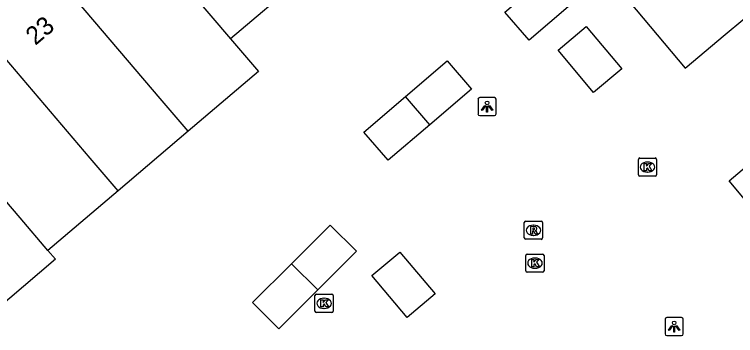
# Model space of a CAD drawing. Extents: x 160379 to 161131, y 383940 to 384849.
# Drawn here: x 160708.69 to 160748.4, y 384618.48 to 384636.19 of the extents above; entities that cross this region are included whole.
import ezdxf

# ---------------------------------------------------------------- set-up
doc = ezdxf.new("R2010")
doc.units = 0
for name, color, linetype in [('IMGEO_Kolk', 7, 'Continuous'), ('IMGEO_Lichtpunt', 7, 'Continuous'), ('IMGEO_Pand', 7, 'Continuous'), ('IMGEO_Pand_nummerreeks', 7, 'Continuous'), ('IMGEO_Rioolput', 7, 'Continuous')]:
    doc.layers.add(name, color=color, linetype=linetype)

msp = doc.modelspace()

# ---------------------------------------------------------------- linework, layer by layer
at = {"layer": 'IMGEO_Kolk'}
for p, q in [((160743.047, 384627.346), (160743.047, 384628.198)), ((160743.122, 384628.272), (160743.974, 384628.272)), ((160743.535, 384628.052), (160743.56, 384628.052)), ((160744.048, 384628.198), (160744.048, 384627.346)), ((160743.974, 384627.272), (160743.122, 384627.272)), ((160743.558, 384627.492), (160743.533, 384627.492)), ((160736.852, 384622.052), (160736.852, 384622.904)), ((160736.927, 384622.978), (160737.779, 384622.978)), ((160737.853, 384622.904), (160737.853, 384622.052)), ((160737.34, 384622.758), (160737.365, 384622.758)), ((160737.363, 384622.198), (160737.338, 384622.198)), ((160737.779, 384621.978), (160736.927, 384621.978)), ((160725.239, 384619.835), (160725.239, 384620.687)), ((160725.314, 384620.761), (160726.166, 384620.761)), ((160725.727, 384620.541), (160725.752, 384620.541)), ((160726.24, 384620.687), (160726.24, 384619.835)), ((160726.166, 384619.761), (160725.314, 384619.761)), ((160725.75, 384619.981), (160725.725, 384619.981))]:
    msp.add_line(p, q, dxfattribs=at)
for points in [[(160743.047, 384627.346), (160743.047, 384628.198)], [(160743.122, 384628.272), (160743.974, 384628.272)], [(160744.048, 384628.198), (160744.048, 384627.346)], [(160743.368, 384627.972), (160743.491, 384627.972), (160743.491, 384627.821), (160743.621, 384627.972), (160743.785, 384627.972), (160743.639, 384627.821), (160743.792, 384627.572), (160743.64, 384627.572), (160743.555, 384627.736), (160743.491, 384627.669), (160743.491, 384627.572), (160743.368, 384627.572), (160743.368, 384627.972)], [(160743.974, 384627.272), (160743.122, 384627.272)], [(160736.852, 384622.052), (160736.852, 384622.904)], [(160736.927, 384622.978), (160737.779, 384622.978)], [(160737.853, 384622.904), (160737.853, 384622.052)], [(160737.173, 384622.678), (160737.296, 384622.678), (160737.296, 384622.527), (160737.426, 384622.678), (160737.59, 384622.678), (160737.444, 384622.527), (160737.597, 384622.278), (160737.445, 384622.278), (160737.36, 384622.442), (160737.296, 384622.375), (160737.296, 384622.278), (160737.173, 384622.278), (160737.173, 384622.678)], [(160737.779, 384621.978), (160736.927, 384621.978)], [(160725.239, 384619.835), (160725.239, 384620.687)], [(160725.314, 384620.761), (160726.166, 384620.761)], [(160725.56, 384620.461), (160725.683, 384620.461), (160725.683, 384620.31), (160725.813, 384620.461), (160725.977, 384620.461), (160725.831, 384620.31), (160725.984, 384620.061), (160725.832, 384620.061), (160725.747, 384620.225), (160725.683, 384620.158), (160725.683, 384620.061), (160725.56, 384620.061), (160725.56, 384620.461)], [(160726.24, 384620.687), (160726.24, 384619.835)], [(160726.166, 384619.761), (160725.314, 384619.761)]]:
    msp.add_lwpolyline(points, dxfattribs=at)
for centre, start, end in [((160743.124, 384628.196), 91.552, 178.448), ((160743.124, 384628.196), 91.552, 178.448), ((160743.972, 384628.196), 1.552, 88.448), ((160743.972, 384628.196), 1.552, 88.448), ((160743.124, 384627.348), 181.552, 268.448), ((160743.124, 384627.348), 181.552, 268.448), ((160743.972, 384627.348), 271.552, 358.448), ((160743.972, 384627.348), 271.552, 358.448), ((160736.929, 384622.902), 91.552, 178.448), ((160736.929, 384622.902), 91.552, 178.448), ((160737.777, 384622.902), 1.552, 88.448), ((160737.777, 384622.902), 1.552, 88.448), ((160736.929, 384622.054), 181.552, 268.448), ((160736.929, 384622.054), 181.552, 268.448), ((160737.777, 384622.054), 271.552, 358.448), ((160737.777, 384622.054), 271.552, 358.448), ((160725.316, 384620.685), 91.552, 178.448), ((160725.316, 384620.685), 91.552, 178.448), ((160726.164, 384620.685), 1.552, 88.448), ((160726.164, 384620.685), 1.552, 88.448), ((160725.316, 384619.837), 181.552, 268.448), ((160725.316, 384619.837), 181.552, 268.448), ((160726.164, 384619.837), 271.552, 358.448), ((160726.164, 384619.837), 271.552, 358.448)]:
    msp.add_arc(centre, 0.0765, start, end, dxfattribs=at)
for centre, major_axis, ratio, start_param, end_param in [((160743.534, 384627.772), (-0.387, 0.002), 0.722429, 4.712389, 7.853982), ((160743.559, 384627.772), (-0.39, 0.002), 0.717154, 1.570796, 4.712389), ((160737.339, 384622.478), (-0.387, 0.002), 0.722429, 4.712389, 7.853982), ((160737.364, 384622.478), (-0.39, 0.002), 0.717154, 1.570796, 4.712389), ((160725.726, 384620.261), (-0.387, 0.002), 0.722429, 4.712389, 7.853982), ((160725.751, 384620.261), (-0.39, 0.002), 0.717154, 1.570796, 4.712389)]:
    msp.add_ellipse(centre, major_axis=major_axis, ratio=ratio, start_param=start_param, end_param=end_param, dxfattribs=at)
at = {"layer": 'IMGEO_Lichtpunt'}
for p, q in [((160735.118, 384631.606), (160734.31, 384631.606)), ((160735.118, 384631.606), (160734.31, 384631.606)), ((160734.216, 384631.511), (160734.216, 384630.704)), ((160734.216, 384631.511), (160734.216, 384630.704)), ((160735.212, 384630.704), (160735.212, 384631.511)), ((160735.212, 384630.704), (160735.212, 384631.511)), ((160734.31, 384630.61), (160735.118, 384630.61)), ((160734.31, 384630.61), (160735.118, 384630.61)), ((160744.52, 384619.384), (160744.52, 384618.577)), ((160744.52, 384619.384), (160744.52, 384618.577)), ((160745.422, 384619.479), (160744.614, 384619.479)), ((160745.422, 384619.479), (160744.614, 384619.479)), ((160745.516, 384618.577), (160745.516, 384619.384)), ((160745.516, 384618.577), (160745.516, 384619.384)), ((160744.614, 384618.483), (160745.422, 384618.483)), ((160744.614, 384618.483), (160745.422, 384618.483))]:
    msp.add_line(p, q, dxfattribs=at)
for points in [[(160734.59, 384631.175), (160734.629, 384631.147), (160734.441, 384630.885), (160734.403, 384630.912), (160734.59, 384631.175)], [(160734.802, 384631.147), (160734.84, 384631.174), (160735.027, 384630.912), (160734.988, 384630.884), (160734.802, 384631.147)], [(160734.692, 384631.127), (160734.739, 384631.127), (160734.739, 384630.805), (160734.692, 384630.805), (160734.692, 384631.127)], [(160744.894, 384619.048), (160744.933, 384619.02), (160744.745, 384618.758), (160744.707, 384618.785), (160744.894, 384619.048)], [(160744.996, 384619), (160745.043, 384619), (160745.043, 384618.678), (160744.996, 384618.678), (160744.996, 384619)], [(160745.106, 384619.02), (160745.144, 384619.047), (160745.331, 384618.785), (160745.292, 384618.757), (160745.106, 384619.02)]]:
    msp.add_lwpolyline(points, dxfattribs=at)
for centre in [(160734.715, 384631.309), (160745.019, 384619.182)]:
    msp.add_circle(centre, 0.0994, dxfattribs=at)
for centre, start, end in [((160734.31, 384631.511), 90, 180), ((160734.31, 384631.511), 90, 180), ((160735.118, 384631.511), 0, 90), ((160735.118, 384631.511), 0, 90), ((160734.31, 384630.704), 180, 270), ((160734.31, 384630.704), 180, 270), ((160735.118, 384630.704), 270, 0), ((160735.118, 384630.704), 270, 360), ((160744.614, 384619.384), 90, 180), ((160744.614, 384619.384), 90, 180), ((160745.422, 384619.384), 0, 90), ((160745.422, 384619.384), 0, 90), ((160744.614, 384618.577), 180, 270), ((160744.614, 384618.577), 180, 270), ((160745.422, 384618.577), 270, 0), ((160745.422, 384618.577), 270, 360)]:
    msp.add_arc(centre, 0.0946, start, end, dxfattribs=at)
at = {"layer": 'IMGEO_Pand'}
for points in [[(160755.839, 384641.77), (160752.323, 384645.885), (160744.359, 384639.228), (160742.15, 384637.381), (160745.62, 384633.23), (160747.828, 384635.077), (160748.794, 384635.885), (160752.317, 384638.828), (160755.839, 384641.77)], [(160714.642, 384641.826), (160720.588, 384634.847)], [(160718.264, 384629.748), (160716.721, 384631.559), (160710.78, 384638.533)], [(160724.452, 384638.139), (160720.588, 384634.847)], [(160739.315, 384636.719), (160737.032, 384634.766), (160735.694, 384636.303), (160737.988, 384638.268)], [(160740.58, 384631.89), (160738.627, 384634.209), (160740.175, 384635.52), (160742.128, 384633.182), (160740.58, 384631.89)], [(160714.4, 384626.456), (160712.86, 384628.264), (160706.918, 384635.239)], [(160720.588, 384634.847), (160722.127, 384633.04), (160718.264, 384629.748)], [(160730.225, 384631.665), (160732.526, 384633.625), (160733.866, 384632.058), (160731.558, 384630.099)], [(160710.537, 384623.165), (160710.942, 384622.689), (160706.66, 384619.033), (160704.491, 384621.131), (160698.547, 384628.1), (160703.054, 384631.943)], [(160710.537, 384623.165), (160708.996, 384624.972), (160703.054, 384631.943)], [(160731.558, 384630.099), (160729.263, 384628.151), (160727.923, 384629.705), (160730.225, 384631.665)], [(160731.558, 384630.099), (160730.225, 384631.665)], [(160718.264, 384629.748), (160714.4, 384626.456)], [(160749.997, 384624.688), (160748.043, 384627.014), (160749.582, 384628.317), (160751.538, 384625.992), (160749.997, 384624.688)], [(160714.4, 384626.456), (160710.537, 384623.165)], [(160723.945, 384622.445), (160726.079, 384624.576), (160727.53, 384623.133), (160725.391, 384620.997)], [(160730.319, 384619.489), (160728.366, 384621.789), (160729.912, 384623.087), (160731.857, 384620.79), (160730.319, 384619.489)], [(160725.391, 384620.997), (160723.252, 384618.861), (160721.807, 384620.311), (160723.945, 384622.445)], [(160725.391, 384620.997), (160723.945, 384622.445)]]:
    msp.add_lwpolyline(points, dxfattribs=at)
at = {"layer": 'IMGEO_Rioolput'}
for p, q in [((160736.765, 384623.863), (160736.765, 384624.715)), ((160736.84, 384624.789), (160737.692, 384624.789)), ((160737.253, 384624.569), (160737.278, 384624.569)), ((160737.766, 384624.715), (160737.766, 384623.863)), ((160737.276, 384624.009), (160737.251, 384624.009)), ((160737.692, 384623.789), (160736.84, 384623.789))]:
    msp.add_line(p, q, dxfattribs=at)
for points in [[(160736.765, 384623.863), (160736.765, 384624.715)], [(160736.84, 384624.789), (160737.692, 384624.789)], [(160737.354, 384624.487), (160737.102, 384624.489), (160737.102, 384624.089)], [(160737.28, 384624.408), (160737.226, 384624.408), (160737.226, 384624.327)], [(160737.766, 384624.715), (160737.766, 384623.863)], [(160737.102, 384624.089), (160737.226, 384624.089), (160737.226, 384624.251), (160737.237, 384624.251)], [(160737.226, 384624.327), (160737.278, 384624.327)], [(160737.284, 384624.222), (160737.355, 384624.089), (160737.495, 384624.089), (160737.43, 384624.215)], [(160737.692, 384623.789), (160736.84, 384623.789)]]:
    msp.add_lwpolyline(points, dxfattribs=at)
for centre, radius, start, end in [((160736.842, 384624.713), 0.0765, 91.552, 178.448), ((160736.842, 384624.713), 0.0765, 91.552, 178.448), ((160737.286, 384624.312), 0.0964, 77.0061, 93.1865), ((160737.3, 384624.369), 0.0378, 276.6634, 79.6772), ((160737.353, 384624.377), 0.109, 350.3612, 89.416), ((160737.69, 384624.713), 0.0765, 1.552, 88.448), ((160737.69, 384624.713), 0.0765, 1.552, 88.448), ((160737.236, 384624.198), 0.0533, 26.0293, 88.6989), ((160737.262, 384624.516), 0.19, 274.7715, 282.9687), ((160737.351, 384624.377), 0.112, 277.5842, 350.9817), ((160737.335, 384624.162), 0.108, 29.5134, 73.7905), ((160736.842, 384623.865), 0.0765, 181.552, 268.448), ((160736.842, 384623.865), 0.0765, 181.552, 268.448), ((160737.69, 384623.865), 0.0765, 271.552, 358.448), ((160737.69, 384623.865), 0.0765, 271.552, 358.448)]:
    msp.add_arc(centre, radius, start, end, dxfattribs=at)
for centre, major_axis, ratio, start_param, end_param in [((160737.252, 384624.289), (-0.387, 0.002), 0.722429, 4.712389, 7.853982), ((160737.277, 384624.289), (-0.39, 0.002), 0.717154, 1.570796, 4.712389)]:
    msp.add_ellipse(centre, major_axis=major_axis, ratio=ratio, start_param=start_param, end_param=end_param, dxfattribs=at)

# ---------------------------------------------------------------- texts
at = {"layer": 'IMGEO_Pand_nummerreeks'}
msp.add_text('23', height=1, rotation=40.4565, dxfattribs=at).set_placement((160709.842, 384634.448))

doc.saveas('drawing.dxf')
